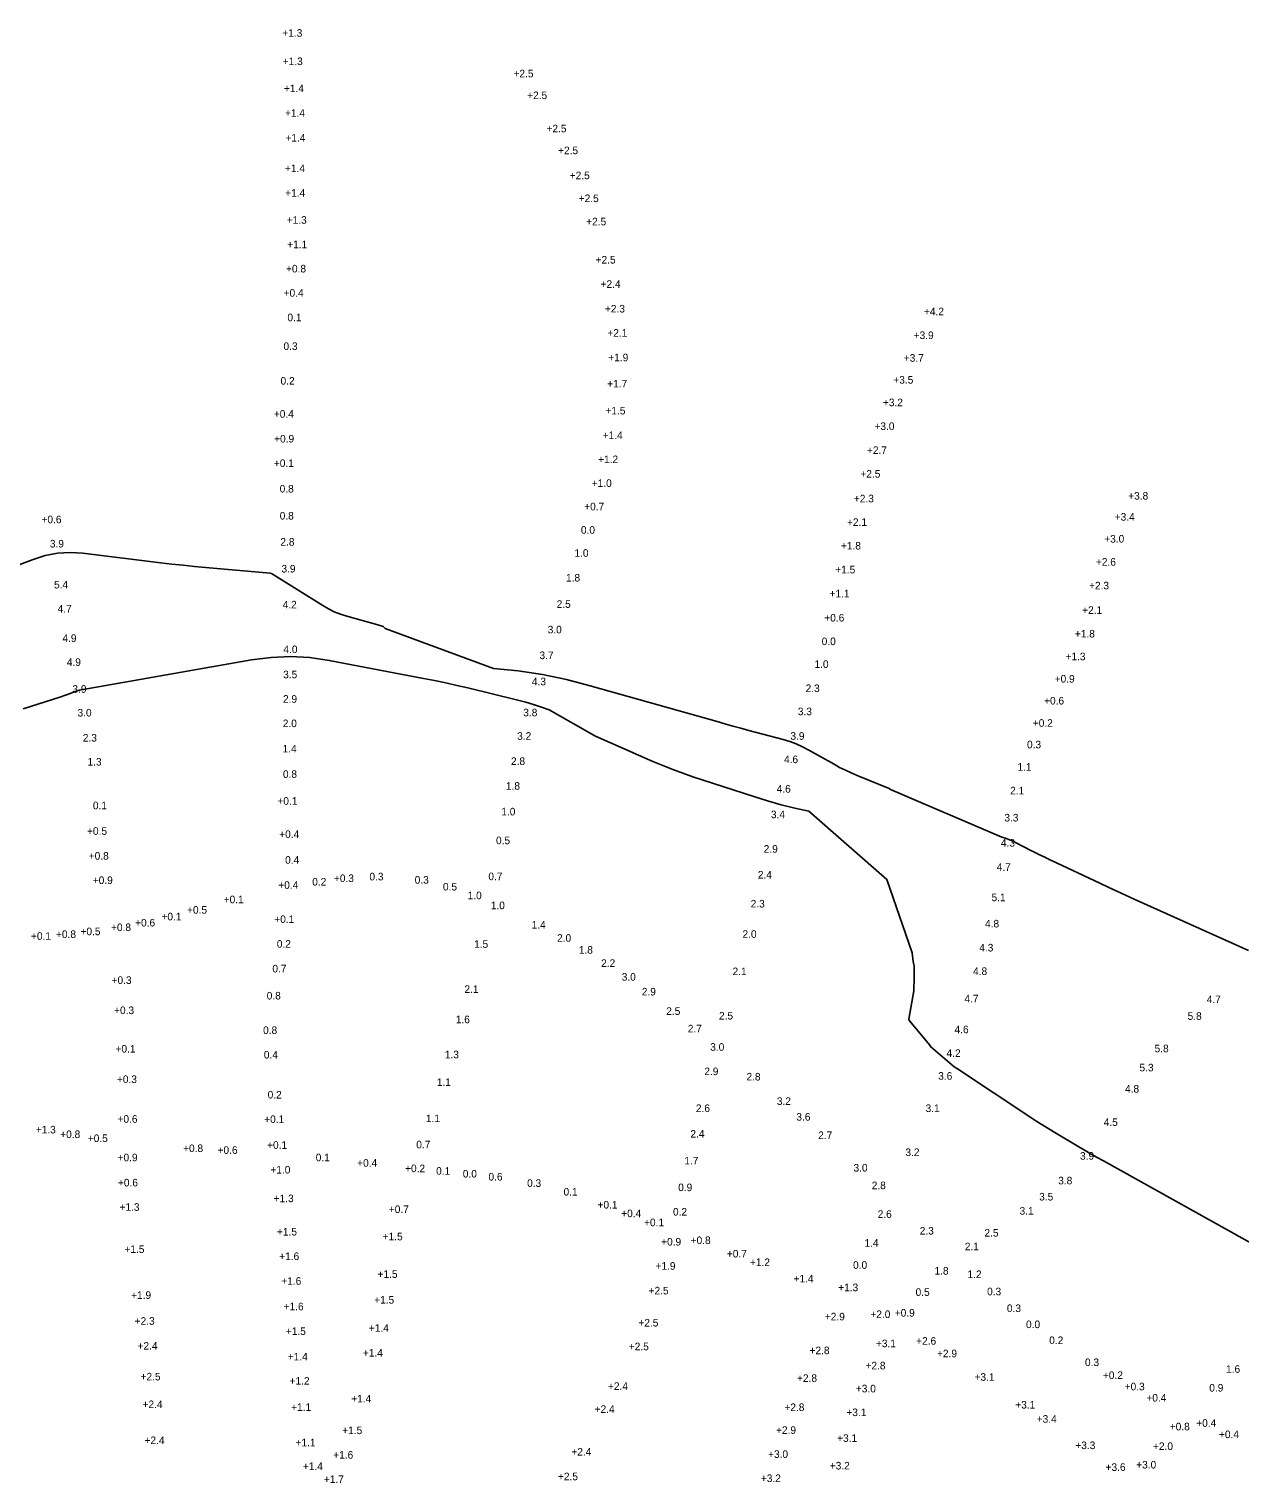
# Model space of a CAD drawing. Extents: x 837127 to 848654, y 3074248 to 3079868.
# Drawn here: x 843732 to 844231, y 3079268 to 3079868 of the extents above; entities that cross this region are included whole.
import ezdxf

# ---------------------------------------------------------------- set-up
doc = ezdxf.new("R2010")
doc.units = 0
for name, color, linetype in [('V-HYDS-MAJR', 7, 'Continuous'), ('V-HYDS-SOUN', 7, 'Continuous'), ('V-HYDS-SOUN-EXSS', 7, 'Continuous')]:
    doc.layers.add(name, color=color, linetype=linetype)

msp = doc.modelspace()

# ---------------------------------------------------------------- linework, layer by layer
at = {"layer": 'V-HYDS-MAJR'}
for points in [[(843713.76, 3079641.71), (843733.68, 3079649.25), (843738.69, 3079650.81), (843743.79, 3079651.75), (843748.96, 3079652.06), (843754.21, 3079651.74), (843786.23, 3079647.87), (843790.88, 3079647.32), (843795.52, 3079646.81), (843800.18, 3079646.34), (843804.83, 3079645.9), (843831.4, 3079643.51), (843831.92, 3079643.43), (843853.09, 3079630.18), (843855.45, 3079628.82), (843857.89, 3079627.65), (843860.4, 3079626.65), (843863, 3079625.83), (843875.84, 3079622.3), (843878.1, 3079621.48), (843878.85, 3079620.69), (843923.55, 3079604.23), (843933.66, 3079603.21), (843943.69, 3079601.68), (843953.62, 3079599.66), (843963.47, 3079597.13), (844015.73, 3079582.29), (844019, 3079581.37), (844022.27, 3079580.46), (844025.55, 3079579.57), (844028.83, 3079578.69), (844042.98, 3079574.92), (844045.72, 3079574.1), (844048.4, 3079573.1), (844051.01, 3079571.94), (844053.55, 3079570.6), (844063.97, 3079564.69), (844066.29, 3079563.42), (844068.65, 3079562.23), (844071.05, 3079561.12), (844073.49, 3079560.08), (844086.65, 3079554.71), (844087.31, 3079554.33), (844133.24, 3079534.67), (844134.67, 3079534.23), (844136.08, 3079533.72), (844137.45, 3079533.14), (844138.8, 3079532.49), (844145.46, 3079529.05), (844146.13, 3079528.7), (844146.81, 3079528.36), (844147.48, 3079528.02), (844148.16, 3079527.68), (844150.88, 3079526.34), (844151.56, 3079526.01), (844152.24, 3079525.68), (844152.93, 3079525.35), (844153.61, 3079525.03), (844173.54, 3079515.69), (844177.09, 3079514.03), (844180.65, 3079512.39), (844184.22, 3079510.75), (844187.79, 3079509.13), (844234.95, 3079487.84)], [(844240.68, 3079364.52), (844175.06, 3079401.09), (844172.53, 3079402.52), (844170.01, 3079403.95), (844167.5, 3079405.41), (844164.99, 3079406.87), (844155, 3079412.78), (844152.51, 3079414.28), (844150.05, 3079415.8), (844147.6, 3079417.36), (844145.17, 3079418.95), (844114.84, 3079439.09), (844113.46, 3079439.86), (844103.96, 3079448.09), (844103.41, 3079448.96), (844095.17, 3079458.79), (844094.93, 3079459.16), (844094.83, 3079459.54), (844096.85, 3079471.21), (844096.9, 3079472.31), (844096.94, 3079473.4), (844096.97, 3079474.5), (844096.99, 3079475.59), (844097.06, 3079480.91), (844097.04, 3079481.53), (844096.94, 3079482.13), (844096.77, 3079482.72), (844096.54, 3079483.3), (844096.13, 3079486.94), (844085.73, 3079517.2), (844053.57, 3079545.32), (844047.84, 3079546.6), (844042.15, 3079548.05), (844036.5, 3079549.64), (844030.89, 3079551.39), (844005.81, 3079559.59), (844001.62, 3079561.02), (843997.46, 3079562.55), (843993.34, 3079564.19), (843989.25, 3079565.92), (843965.59, 3079576.31), (843965.29, 3079576.49), (843946.54, 3079587.12), (843943.34, 3079588.31), (843940.1, 3079589.39), (843936.83, 3079590.35), (843933.53, 3079591.21), (843912.93, 3079596.18), (843908.38, 3079597.25), (843903.82, 3079598.26), (843899.25, 3079599.22), (843894.67, 3079600.12), (843855.83, 3079607.53), (843847.83, 3079608.69), (843839.82, 3079609.11), (843831.8, 3079608.81), (843823.78, 3079607.77), (843754.26, 3079595.6), (843753.43, 3079595.44), (843752.61, 3079595.23), (843751.81, 3079594.99), (843751.01, 3079594.7), (843747.85, 3079593.49), (843747.06, 3079593.2), (843746.26, 3079592.91), (843745.46, 3079592.64), (843744.65, 3079592.38), (843729.59, 3079587.64)]]:
    msp.add_lwpolyline(points, dxfattribs=at)

# ---------------------------------------------------------------- texts
at = {"layer": 'V-HYDS-SOUN'}
for s, p in [('+1.3 ', (843836.45, 3079864.81)), ('+1.3 ', (843836.62, 3079853.13)), ('+2.5 ', (843931.79, 3079848.08)), ('+1.4 ', (843837.11, 3079841.96)), ('+2.5 ', (843937.42, 3079839.1)), ('+1.4 ', (843837.56, 3079831.81)), ('+2.5 ', (843945.4, 3079825.4)), ('+1.4 ', (843837.73, 3079821.57)), ('+2.5 ', (843950.17, 3079816.37)), ('+1.4 ', (843837.55, 3079808.99)), ('+2.5 ', (843954.98, 3079806.05)), ('+1.4 ', (843837.62, 3079798.82)), ('+2.5 ', (843958.68, 3079796.6)), ('+1.3 ', (843838.29, 3079787.68)), ('+2.5 ', (843961.78, 3079787.02)), ('+1.1 ', (843838.46, 3079777.58)), ('+2.5 ', (843965.65, 3079771.27)), ('+0.8 ', (843837.98, 3079767.59)), ('+0.4 ', (843837, 3079757.59)), ('+2.4 ', (843967.71, 3079761.24)), ('+2.3 ', (843969.49, 3079751.07)), ('+4.2 ', (844101.06, 3079749.94)), ('+2.1 ', (843970.49, 3079741.09)), ('+3.9 ', (844096.81, 3079740.13)), ('0.3', (843836.94, 3079735.61)), ('+1.9 ', (843970.89, 3079730.95)), ('+3.7 ', (844092.74, 3079730.76)), ('0.2', (843835.72, 3079721.31)), ('+1.7 ', (843970.44, 3079720.14)), ('+3.5 ', (844088.42, 3079721.74)), ('+0.4 ', (843832.96, 3079707.68)), ('+1.5 ', (843969.7, 3079709.03)), ('+3.2 ', (844084.13, 3079712.42)), ('+3.0 ', (844080.64, 3079702.6)), ('+0.9 ', (843833.07, 3079697.43)), ('+1.4 ', (843968.59, 3079698.86)), ('+2.7 ', (844077.54, 3079692.71)), ('+0.1 ', (843832.96, 3079687.36)), ('+1.2 ', (843966.68, 3079688.94)), ('+1.0 ', (843964.05, 3079679.11)), ('+2.5 ', (844074.83, 3079682.96)), ('0.8', (843835.35, 3079676.81)), ('+2.3 ', (844072.16, 3079672.75)), ('+3.8 ', (844185.29, 3079673.89)), ('+0.7 ', (843960.96, 3079669.46)), ('+0.6 ', (843737.14, 3079664.13)), ('0.8', (843835.37, 3079665.66)), (' 0.0', (843958.42, 3079659.81)), ('+2.1 ', (844069.33, 3079663.03)), ('+3.4 ', (844179.73, 3079665.21)), ('3.9', (843740.58, 3079654.14)), ('2.8', (843835.67, 3079654.89)), ('+3.0 ', (844175.41, 3079656.15)), ('1.0', (843956.92, 3079650.31)), ('+1.8 ', (844066.82, 3079653.31)), ('3.9', (843836.09, 3079643.82)), ('+1.5 ', (844064.48, 3079643.45)), ('+2.6 ', (844171.97, 3079646.63)), ('5.4', (843742.31, 3079637.24)), ('1.8', (843953.44, 3079640.1)), ('+2.3 ', (844169.13, 3079636.85)), ('+1.1 ', (844062.12, 3079633.57)), ('4.7', (843743.79, 3079627.3)), ('4.2', (843836.59, 3079629)), ('2.5', (843949.6, 3079629.24)), ('+2.1 ', (844166.3, 3079626.76)), ('3.0', (843945.89, 3079618.71)), ('+0.6 ', (844059.96, 3079623.59)), ('4.9', (843745.76, 3079615.16)), (' 0.0', (844057.73, 3079613.86)), ('+1.8 ', (844163.3, 3079617.01)), ('4.0', (843836.9, 3079610.58)), ('3.7', (843942.5, 3079608.1)), ('+1.3 ', (844159.42, 3079607.62)), ('4.9', (843747.58, 3079605.29)), ('3.5', (843836.8, 3079600.19)), ('1.0', (844055.91, 3079604.45)), ('3.9', (843749.88, 3079594.2)), ('4.3', (843939.37, 3079597.28)), ('2.3', (844052.26, 3079594.51)), ('+0.9 ', (844154.97, 3079598.41)), ('2.9', (843836.72, 3079590.09)), ('+0.6 ', (844150.6, 3079589.36)), ('3.0', (843752, 3079584.42)), ('3.8', (843935.81, 3079584.49)), ('3.3', (844049.05, 3079584.94)), ('2.0', (843836.64, 3079580.03)), ('+0.2 ', (844145.95, 3079580.18)), ('2.3', (843754.18, 3079574.08)), ('3.2', (843933.3, 3079574.81)), ('3.9', (844045.98, 3079574.82)), ('0.3', (844143.56, 3079571.3)), ('1.3', (843756.12, 3079564.19)), ('1.4', (843836.56, 3079569.59)), ('2.8', (843930.75, 3079564.42)), ('4.6', (844043.34, 3079565.17)), ('0.8', (843836.7, 3079559.12)), ('1.1', (844139.61, 3079562.07)), ('1.8', (843928.65, 3079554.21)), ('4.6', (844040.32, 3079553.01)), ('2.1', (844136.6, 3079552.29)), ('0.1', (843758.33, 3079546.16)), ('+0.1 ', (843834.42, 3079548.02)), ('1.0', (843926.76, 3079543.62)), ('3.4', (844037.95, 3079542.47)), ('3.3', (844134.21, 3079541.12)), ('+0.5 ', (843755.92, 3079535.62)), ('+0.4 ', (843835.18, 3079534.3)), ('0.5', (843924.57, 3079531.74)), ('2.9', (844034.97, 3079528.24)), ('4.3', (844132.77, 3079530.76)), ('+0.8 ', (843756.62, 3079525.37)), ('0.4', (843837.61, 3079523.69)), ('+0.3 ', (843857.73, 3079516.14)), ('0.3', (843872.37, 3079516.83)), ('0.7', (843921.41, 3079516.89)), ('2.4', (844032.55, 3079517.58)), ('4.7', (844131.04, 3079520.74)), ('+0.9 ', (843758.28, 3079515.33)), ('+0.4 ', (843834.79, 3079513.34)), ('0.2', (843848.78, 3079514.69)), ('0.3', (843891.04, 3079515.47)), ('0.5', (843902.7, 3079512.66)), ('+0.1 ', (843812.27, 3079507.38)), ('1.0', (843912.88, 3079509.05)), ('1.0', (843922.41, 3079504.93)), ('2.3', (844029.6, 3079505.64)), ('5.1', (844128.94, 3079508.24)), ('+0.6 ', (843775.76, 3079497.79)), ('+0.1 ', (843786.61, 3079500.33)), ('+0.5 ', (843797.16, 3079503.09)), ('+0.1 ', (843833.15, 3079499.25)), ('+0.1 ', (843732.81, 3079492.3)), ('+0.8 ', (843743.12, 3079493.06)), ('+0.5 ', (843753.22, 3079494.2)), ('+0.8 ', (843765.81, 3079495.9)), ('1.4', (843939.28, 3079496.93)), ('2.0', (844026.23, 3079493.12)), ('4.8', (844126.24, 3079497.4)), ('0.2', (843834.18, 3079489.05)), ('1.5', (843915.54, 3079489.01)), ('2.0', (843949.76, 3079491.5)), ('4.3', (844123.88, 3079487.5)), ('2.2', (843967.92, 3079481.12)), ('+0.3 ', (843766.04, 3079474.11)), ('0.7', (843832.34, 3079478.86)), ('3.0', (843976.42, 3079475.46)), ('2.1', (844022.13, 3079477.72)), ('4.8', (844121.31, 3079477.78)), ('2.1', (843911.55, 3079470.41)), ('2.9', (843984.7, 3079469.35)), ('0.8', (843830.02, 3079467.69)), ('4.7', (844117.76, 3079466.5)), ('4.7', (844217.68, 3079466.18)), ('+0.3 ', (843767.07, 3079461.66)), ('1.6', (843907.98, 3079457.89)), ('2.5', (843994.78, 3079461.33)), ('2.5', (844016.53, 3079459.43)), ('5.8', (844209.79, 3079459.29)), ('0.8', (843828.52, 3079453.45)), ('2.7', (844003.67, 3079454.11)), ('4.6', (844113.67, 3079453.77)), ('+0.1 ', (843767.66, 3079445.78)), ('3.0', (844012.91, 3079446.54)), ('4.2', (844110.38, 3079444.01)), ('5.8', (844196.16, 3079445.91)), ('0.4', (843828.83, 3079443.33)), ('1.3', (843903.46, 3079443.41)), ('5.3', (844189.94, 3079438.03)), ('+0.3 ', (843768.25, 3079433.23)), ('1.1', (843900.16, 3079432.01)), ('2.9', (844010.49, 3079436.48)), ('2.8', (844027.86, 3079434.28)), ('3.6', (844106.94, 3079434.59)), ('0.2', (843830.4, 3079426.84)), ('4.8', (844183.98, 3079429.29)), ('2.6', (844007.01, 3079421.27)), ('3.2', (844040.4, 3079424.2)), ('3.1', (844101.73, 3079421.26)), ('+0.6 ', (843768.48, 3079416.84)), ('+0.1 ', (843828.98, 3079416.74)), ('1.1', (843895.67, 3079417.09)), ('3.6', (844048.44, 3079417.72)), ('4.5', (844175.18, 3079415.52)), ('+1.3 ', (843734.79, 3079412.44)), ('+0.8 ', (843744.86, 3079410.53)), ('+0.5 ', (843756.23, 3079408.89)), ('2.4', (844004.74, 3079410.71)), ('2.7', (844057.44, 3079410.12)), ('+0.8 ', (843795.53, 3079404.75)), ('+0.6 ', (843809.75, 3079404.01)), ('+0.1 ', (843830.17, 3079406.08)), ('0.7', (843891.69, 3079406.29)), ('3.2', (844093.41, 3079403.12)), ('+0.9 ', (843768.52, 3079400.95)), ('+1.0 ', (843831.53, 3079395.9)), ('0.1', (843850.23, 3079400.95)), ('+0.4 ', (843867.32, 3079398.7)), ('+0.2 ', (843887.08, 3079396.45)), ('1.7', (844002.23, 3079399.64)), ('3.0', (844071.99, 3079396.72)), ('3.9', (844165.42, 3079401.6)), ('+0.6 ', (843768.66, 3079390.57)), ('0.1', (843899.89, 3079395.41)), (' 0.0', (843909.72, 3079394.25)), ('0.6', (843921.47, 3079393.01)), ('0.3', (843937.4, 3079390.4)), ('3.8', (844156.42, 3079391.42)), ('+1.3 ', (843832.88, 3079384.08)), ('0.1', (843952.43, 3079386.82)), ('0.9', (843999.7, 3079388.62)), ('2.8', (844079.52, 3079389.44)), ('3.5', (844148.57, 3079384.78)), ('+1.3 ', (843769.3, 3079380.51)), ('+0.7 ', (843880.38, 3079379.61)), ('+0.1 ', (843966.45, 3079381.45)), ('+0.4 ', (843976.21, 3079377.89)), ('0.2', (843997.56, 3079378.55)), ('3.1', (844140.49, 3079378.94)), ('+0.1 ', (843985.62, 3079374.15)), ('2.6', (844081.98, 3079377.61)), ('+1.5 ', (843834.25, 3079370.33)), ('+1.5 ', (843877.83, 3079368.36)), ('+0.9 ', (843992.68, 3079366.19)), ('+0.8 ', (844004.85, 3079366.8)), ('2.3', (844099.32, 3079370.74)), ('2.5', (844126, 3079369.87)), ('+1.5 ', (843771.35, 3079363.14)), ('+1.6 ', (843835.16, 3079360.21)), ('+0.7 ', (844019.79, 3079361.26)), ('1.4', (844076.53, 3079365.72)), ('2.1', (844117.9, 3079364.23)), ('+1.9 ', (843990.34, 3079356.21)), ('+1.2 ', (844029.31, 3079357.74)), (' 0.0', (844070.67, 3079356.59)), ('1.8', (844105.4, 3079354.21)), ('+1.6 ', (843836.03, 3079350.01)), ('+1.5 ', (843875.71, 3079352.85)), ('+1.4 ', (844047.26, 3079350.97)), ('1.2', (844119.01, 3079352.77)), ('+1.9 ', (843774.09, 3079344.17)), ('+1.5 ', (843874.33, 3079342.22)), ('+2.5 ', (843987.5, 3079346.02)), ('+1.3 ', (844065.69, 3079347.36)), ('0.5', (844097.61, 3079345.42)), ('0.3', (844127.1, 3079345.67)), ('+1.6 ', (843836.99, 3079339.48)), ('+2.0 ', (844078.96, 3079336.3)), ('+0.9 ', (844089.02, 3079336.87)), ('0.3', (844135.27, 3079338.77)), ('+2.3 ', (843775.56, 3079333.5)), ('+1.4 ', (843872.12, 3079330.6)), ('+2.5 ', (843983.29, 3079332.79)), ('+2.9 ', (844060.18, 3079335.32)), (' 0.0', (844141.99, 3079332.12)), ('+1.5 ', (843837.9, 3079329.31)), ('+3.1 ', (844081.25, 3079324.24)), ('+2.6 ', (844097.84, 3079325.3)), ('0.2', (844152.71, 3079325.56)), ('+2.4 ', (843776.75, 3079323.26)), ('+1.4 ', (843838.7, 3079318.8)), ('+1.4 ', (843869.66, 3079320.37)), ('+2.5 ', (843979.34, 3079323)), ('+2.8 ', (844053.88, 3079321.38)), ('+2.9 ', (844106.44, 3079320.1)), ('+2.8 ', (844076.95, 3079315.11)), ('0.3', (844167.45, 3079316.47)), ('1.6', (844225.64, 3079313.69)), ('+2.5 ', (843777.99, 3079310.55)), ('+1.2 ', (843839.44, 3079308.81)), ('+2.4 ', (843970.75, 3079306.63)), ('+2.8 ', (844048.71, 3079309.95)), ('+3.1 ', (844121.9, 3079310.41)), ('+0.2 ', (844174.86, 3079311.15)), ('+0.3 ', (844183.84, 3079306.47)), ('0.9', (844218.72, 3079305.95)), ('+1.4 ', (843864.88, 3079301.47)), ('+3.0 ', (844072.98, 3079305.62)), ('+0.4 ', (844192.78, 3079301.83)), ('+2.4 ', (843778.81, 3079299.14)), ('+1.1 ', (843840.08, 3079297.97)), ('+2.4 ', (843965.25, 3079297.16)), ('+2.8 ', (844043.52, 3079297.92)), ('+3.1 ', (844069.06, 3079295.83)), ('+3.1 ', (844138.73, 3079298.96)), ('+1.5 ', (843861.16, 3079288.41)), ('+2.9 ', (844040.06, 3079288.5)), ('+3.4 ', (844147.56, 3079293.1)), ('+0.8 ', (844202.43, 3079289.96)), ('+0.4 ', (844213.35, 3079291.42)), ('+2.4 ', (843779.62, 3079284.28)), ('+1.1 ', (843841.92, 3079283.36)), ('+3.1 ', (844065.24, 3079285.21)), ('+3.3 ', (844163.48, 3079282.22)), ('+2.0 ', (844195.51, 3079281.86)), ('+0.4 ', (844222.72, 3079286.74)), ('+1.6 ', (843857.45, 3079278.29)), ('+2.4 ', (843955.65, 3079279.56)), ('+3.0 ', (844036.77, 3079278.58)), ('+1.4 ', (843844.92, 3079273.59)), ('+3.2 ', (844062.21, 3079273.82)), ('+3.6 ', (844175.95, 3079273.24)), ('+3.0 ', (844188.59, 3079274.22)), ('+1.7 ', (843853.58, 3079268.27)), ('+2.5 ', (843950.13, 3079269.39)), ('+3.2 ', (844033.8, 3079268.64))]:
    msp.add_text(s, height=3.125, dxfattribs=at).set_placement(p)
at = {"layer": 'V-HYDS-SOUN-EXSS'}
for s, p in [('0.1', (843838.55, 3079747.45)), ('1.8', (843958.71, 3079486.59))]:
    msp.add_text(s, height=3.125, dxfattribs=at).set_placement(p)

doc.saveas('drawing.dxf')
